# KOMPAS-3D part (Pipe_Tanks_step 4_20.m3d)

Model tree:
1. X Axis
2. Y Axis
3. Z Axis  (labels: Bend 90 Dn 20; Pipe Dn 20)
     Òîëùèíà ñòåíêè 1 = 1

Referenced files in C:\Documents and Settings\kashirsky\Мои документы\Camtasia Studio\Pipelines3D\Tanks\: Tanks_step 4.a3d
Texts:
  Pipe Dn 50
  Steel ASTM A295
  Three Point Plane
  Plane at Angle
  Line and Point Plane
  Axis through Two Vertices
  Axis of Feature
  Axis of Conical Surface
  Axis through Edge
  Trim by Surface
  Trim by Sketch
  Feature with No History
  Intersection Axis of Two Planes
  Two Line Plane
  Line and Face Plane
  Bend by line
  Hole in sheet body
  Cut in sheet body
  Point in CM
  Linear Dimension from Line to Point
  Surface Finish Symbol
  Geometric Tolerance Symbol
  Leader #1
  Leader #2
  Leader #3
  Shape Deviations and Datum
  Node point number
  Mark of coordination axis
  Node point designation
  Mark/Reference designation with leader
  Mark/reference designation on line
  Mark/Reference designation without leader
  Bend 90 Dn 20
  Pipe Dn 20
  Plane of section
